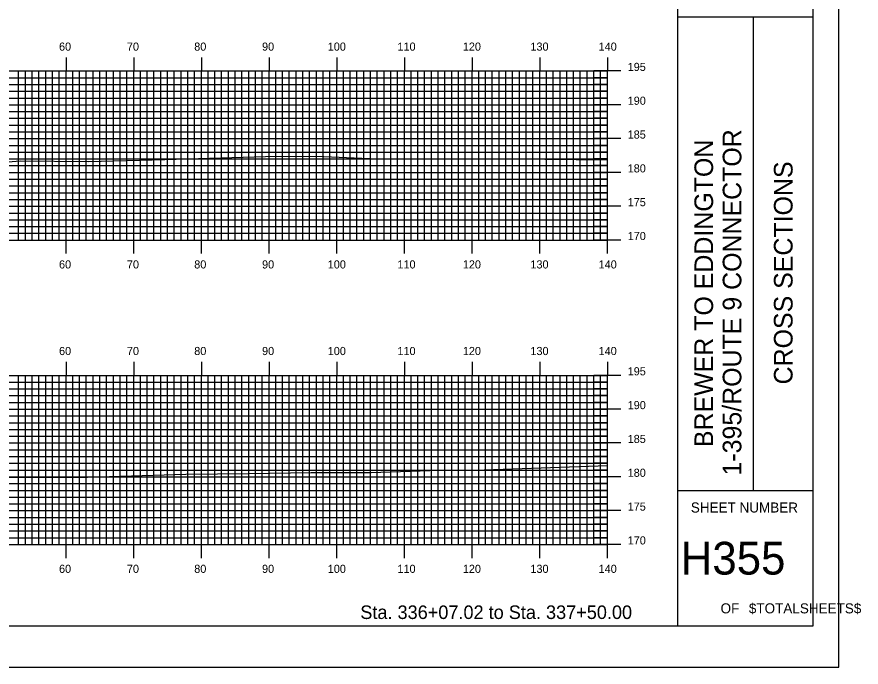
# Model space of a CAD drawing. Extents: x 1823571 to 1823914, y 442310 to 442530.
# Drawn here: x 1823789.6 to 1823914.4, y 442310 to 442406.1 of the extents above; entities that cross this region are included whole.
import ezdxf

# ---------------------------------------------------------------- set-up
doc = ezdxf.new("R2010")
doc.units = 0
for name, color, linetype in [('BORDER', 7, 'Continuous'), ('H_V ANNOTATION', 7, 'Continuous'), ('MAJOR', 7, 'Continuous'), ('MINOR', 7, 'Continuous'), ('PLOT BOUNDARY', 7, 'Continuous'), ('S_Roadway_Centerline', 7, 'Continuous')]:
    doc.layers.add(name, color=color, linetype=linetype)

msp = doc.modelspace()

# ---------------------------------------------------------------- linework, layer by layer
at = {"layer": 'BORDER'}
for p, q in [((1823887.3, 442316.11), (1823887.3, 442526.11)), ((1823887.3, 442406.11), (1823907.3, 442406.11)), ((1823898.48, 442336.11), (1823898.48, 442406.11)), ((1823887.3, 442336.11), (1823907.3, 442336.11))]:
    msp.add_line(p, q, dxfattribs=at)
msp.add_lwpolyline([(1823587.3, 442316.11), (1823907.3, 442316.11), (1823907.3, 442526.11), (1823587.3, 442526.11)], close=True, dxfattribs=at)
at = {"layer": 'MAJOR'}
for p, q in [((1823796.9, 442400.12), (1823796.9, 442398.12)), ((1823806.9, 442400.12), (1823806.9, 442398.12)), ((1823816.9, 442400.12), (1823816.9, 442398.12)), ((1823826.9, 442400.12), (1823826.9, 442398.12)), ((1823836.9, 442400.12), (1823836.9, 442398.12)), ((1823846.9, 442400.12), (1823846.9, 442398.12)), ((1823856.9, 442400.12), (1823856.9, 442398.12)), ((1823866.9, 442400.12), (1823866.9, 442398.12)), ((1823876.9, 442400.12), (1823876.9, 442398.12)), ((1823596.9, 442398.12), (1823876.9, 442398.12)), ((1823596.9, 442398.12), (1823876.9, 442398.12)), ((1823796.9, 442373.12), (1823796.9, 442398.12)), ((1823806.9, 442373.12), (1823806.9, 442398.12)), ((1823816.9, 442373.12), (1823816.9, 442398.12)), ((1823826.9, 442373.12), (1823826.9, 442398.12)), ((1823836.9, 442373.12), (1823836.9, 442398.12)), ((1823846.9, 442373.12), (1823846.9, 442398.12)), ((1823856.9, 442373.12), (1823856.9, 442398.12)), ((1823866.9, 442373.12), (1823866.9, 442398.12)), ((1823878.9, 442398.12), (1823874.9, 442398.12)), ((1823876.9, 442373.12), (1823876.9, 442398.12)), ((1823876.9, 442373.12), (1823876.9, 442398.12)), ((1823596.9, 442393.12), (1823876.9, 442393.12)), ((1823878.9, 442393.12), (1823874.9, 442393.12)), ((1823596.9, 442388.12), (1823876.9, 442388.12)), ((1823878.9, 442388.12), (1823874.9, 442388.12)), ((1823596.9, 442383.12), (1823876.9, 442383.12)), ((1823878.9, 442383.12), (1823874.9, 442383.12)), ((1823596.9, 442378.12), (1823876.9, 442378.12)), ((1823878.9, 442378.12), (1823874.9, 442378.12)), ((1823596.9, 442373.12), (1823876.9, 442373.12)), ((1823796.9, 442371.11), (1823796.9, 442373.12)), ((1823806.9, 442371.11), (1823806.9, 442373.12)), ((1823816.9, 442371.11), (1823816.9, 442373.12)), ((1823826.9, 442371.11), (1823826.9, 442373.12)), ((1823836.9, 442371.11), (1823836.9, 442373.12)), ((1823846.9, 442371.11), (1823846.9, 442373.12)), ((1823856.9, 442371.11), (1823856.9, 442373.12)), ((1823866.9, 442371.11), (1823866.9, 442373.12)), ((1823878.9, 442373.12), (1823874.9, 442373.12)), ((1823876.9, 442371.11), (1823876.9, 442373.12)), ((1823796.9, 442355.12), (1823796.9, 442353.12)), ((1823806.9, 442355.12), (1823806.9, 442353.12)), ((1823816.9, 442355.12), (1823816.9, 442353.12)), ((1823826.9, 442355.12), (1823826.9, 442353.12)), ((1823836.9, 442355.12), (1823836.9, 442353.12)), ((1823846.9, 442355.12), (1823846.9, 442353.12)), ((1823856.9, 442355.12), (1823856.9, 442353.12)), ((1823866.9, 442355.12), (1823866.9, 442353.12)), ((1823876.9, 442355.12), (1823876.9, 442353.12)), ((1823596.9, 442353.12), (1823876.9, 442353.12)), ((1823796.9, 442328.12), (1823796.9, 442353.12)), ((1823806.9, 442328.12), (1823806.9, 442353.12)), ((1823816.9, 442328.12), (1823816.9, 442353.12)), ((1823826.9, 442328.12), (1823826.9, 442353.12)), ((1823836.9, 442328.12), (1823836.9, 442353.12)), ((1823846.9, 442328.12), (1823846.9, 442353.12)), ((1823856.9, 442328.12), (1823856.9, 442353.12)), ((1823866.9, 442328.12), (1823866.9, 442353.12)), ((1823878.9, 442353.12), (1823874.9, 442353.12)), ((1823876.9, 442328.12), (1823876.9, 442353.12)), ((1823876.9, 442328.12), (1823876.9, 442353.12)), ((1823596.9, 442348.12), (1823876.9, 442348.12)), ((1823878.9, 442348.12), (1823874.9, 442348.12)), ((1823596.9, 442343.12), (1823876.9, 442343.12)), ((1823878.9, 442343.12), (1823874.9, 442343.12)), ((1823596.9, 442338.12), (1823876.9, 442338.12)), ((1823878.9, 442338.12), (1823874.9, 442338.12)), ((1823596.9, 442333.12), (1823876.9, 442333.12)), ((1823878.9, 442333.12), (1823874.9, 442333.12)), ((1823596.9, 442328.12), (1823876.9, 442328.12)), ((1823596.9, 442328.12), (1823876.9, 442328.12)), ((1823796.9, 442326.11), (1823796.9, 442328.12)), ((1823806.9, 442326.11), (1823806.9, 442328.12)), ((1823816.9, 442326.11), (1823816.9, 442328.12)), ((1823826.9, 442326.11), (1823826.9, 442328.12)), ((1823836.9, 442326.11), (1823836.9, 442328.12)), ((1823846.9, 442326.11), (1823846.9, 442328.12)), ((1823856.9, 442326.11), (1823856.9, 442328.12)), ((1823866.9, 442326.11), (1823866.9, 442328.12)), ((1823878.9, 442328.12), (1823874.9, 442328.12)), ((1823876.9, 442326.11), (1823876.9, 442328.12))]:
    msp.add_line(p, q, dxfattribs=at)
at = {"layer": 'MINOR'}
for p, q in [((1823789.9, 442373.12), (1823789.9, 442398.12)), ((1823790.9, 442373.12), (1823790.9, 442398.12)), ((1823791.9, 442373.12), (1823791.9, 442398.12)), ((1823792.9, 442373.12), (1823792.9, 442398.12)), ((1823793.9, 442373.12), (1823793.9, 442398.12)), ((1823794.9, 442373.12), (1823794.9, 442398.12)), ((1823795.9, 442373.12), (1823795.9, 442398.12)), ((1823797.9, 442373.12), (1823797.9, 442398.12)), ((1823798.9, 442373.12), (1823798.9, 442398.12)), ((1823799.9, 442373.12), (1823799.9, 442398.12)), ((1823800.9, 442373.12), (1823800.9, 442398.12)), ((1823801.9, 442373.12), (1823801.9, 442398.12)), ((1823802.9, 442373.12), (1823802.9, 442398.12)), ((1823803.9, 442373.12), (1823803.9, 442398.12)), ((1823804.9, 442373.12), (1823804.9, 442398.12)), ((1823805.9, 442373.12), (1823805.9, 442398.12)), ((1823807.9, 442373.12), (1823807.9, 442398.12)), ((1823808.9, 442373.12), (1823808.9, 442398.12)), ((1823809.9, 442373.12), (1823809.9, 442398.12)), ((1823810.9, 442373.12), (1823810.9, 442398.12)), ((1823811.9, 442373.12), (1823811.9, 442398.12)), ((1823812.9, 442373.12), (1823812.9, 442398.12)), ((1823813.9, 442373.12), (1823813.9, 442398.12)), ((1823814.9, 442373.12), (1823814.9, 442398.12)), ((1823815.9, 442373.12), (1823815.9, 442398.12)), ((1823817.9, 442373.12), (1823817.9, 442398.12)), ((1823818.9, 442373.12), (1823818.9, 442398.12)), ((1823819.9, 442373.12), (1823819.9, 442398.12)), ((1823820.9, 442373.12), (1823820.9, 442398.12)), ((1823821.9, 442373.12), (1823821.9, 442398.12)), ((1823822.9, 442373.12), (1823822.9, 442398.12)), ((1823823.9, 442373.12), (1823823.9, 442398.12)), ((1823824.9, 442373.12), (1823824.9, 442398.12)), ((1823825.9, 442373.12), (1823825.9, 442398.12)), ((1823827.9, 442373.12), (1823827.9, 442398.12)), ((1823828.9, 442373.12), (1823828.9, 442398.12)), ((1823829.9, 442373.12), (1823829.9, 442398.12)), ((1823830.9, 442373.12), (1823830.9, 442398.12)), ((1823831.9, 442373.12), (1823831.9, 442398.12)), ((1823832.9, 442373.12), (1823832.9, 442398.12)), ((1823833.9, 442373.12), (1823833.9, 442398.12)), ((1823834.9, 442373.12), (1823834.9, 442398.12)), ((1823835.9, 442373.12), (1823835.9, 442398.12)), ((1823837.9, 442373.12), (1823837.9, 442398.12)), ((1823838.9, 442373.12), (1823838.9, 442398.12)), ((1823839.9, 442373.12), (1823839.9, 442398.12)), ((1823840.9, 442373.12), (1823840.9, 442398.12)), ((1823841.9, 442373.12), (1823841.9, 442398.12)), ((1823842.9, 442373.12), (1823842.9, 442398.12)), ((1823843.9, 442373.12), (1823843.9, 442398.12)), ((1823844.9, 442373.12), (1823844.9, 442398.12)), ((1823845.9, 442373.12), (1823845.9, 442398.12)), ((1823847.9, 442373.12), (1823847.9, 442398.12)), ((1823848.9, 442373.12), (1823848.9, 442398.12)), ((1823849.9, 442373.12), (1823849.9, 442398.12)), ((1823850.9, 442373.12), (1823850.9, 442398.12)), ((1823851.9, 442373.12), (1823851.9, 442398.12)), ((1823852.9, 442373.12), (1823852.9, 442398.12)), ((1823853.9, 442373.12), (1823853.9, 442398.12)), ((1823854.9, 442373.12), (1823854.9, 442398.12)), ((1823855.9, 442373.12), (1823855.9, 442398.12)), ((1823857.9, 442373.12), (1823857.9, 442398.12)), ((1823858.9, 442373.12), (1823858.9, 442398.12)), ((1823859.9, 442373.12), (1823859.9, 442398.12)), ((1823860.9, 442373.12), (1823860.9, 442398.12)), ((1823861.9, 442373.12), (1823861.9, 442398.12)), ((1823862.9, 442373.12), (1823862.9, 442398.12)), ((1823863.9, 442373.12), (1823863.9, 442398.12)), ((1823864.9, 442373.12), (1823864.9, 442398.12)), ((1823865.9, 442373.12), (1823865.9, 442398.12)), ((1823867.9, 442373.12), (1823867.9, 442398.12)), ((1823868.9, 442373.12), (1823868.9, 442398.12)), ((1823869.9, 442373.12), (1823869.9, 442398.12)), ((1823870.9, 442373.12), (1823870.9, 442398.12)), ((1823871.9, 442373.12), (1823871.9, 442398.12)), ((1823872.9, 442373.12), (1823872.9, 442398.12)), ((1823873.9, 442373.12), (1823873.9, 442398.12)), ((1823874.9, 442373.12), (1823874.9, 442398.12)), ((1823875.9, 442373.12), (1823875.9, 442398.12)), ((1823596.9, 442397.12), (1823876.9, 442397.12)), ((1823876.9, 442397.12), (1823874.9, 442397.12)), ((1823596.9, 442396.12), (1823876.9, 442396.12)), ((1823876.9, 442396.12), (1823874.9, 442396.12)), ((1823596.9, 442395.12), (1823876.9, 442395.12)), ((1823876.9, 442395.12), (1823874.9, 442395.12)), ((1823596.9, 442394.12), (1823876.9, 442394.12)), ((1823876.9, 442394.12), (1823874.9, 442394.12)), ((1823596.9, 442392.12), (1823876.9, 442392.12)), ((1823876.9, 442392.12), (1823874.9, 442392.12)), ((1823596.9, 442391.12), (1823876.9, 442391.12)), ((1823876.9, 442391.12), (1823874.9, 442391.12)), ((1823596.9, 442390.12), (1823876.9, 442390.12)), ((1823876.9, 442390.12), (1823874.9, 442390.12)), ((1823596.9, 442389.12), (1823876.9, 442389.12)), ((1823876.9, 442389.12), (1823874.9, 442389.12)), ((1823596.9, 442387.12), (1823876.9, 442387.12)), ((1823876.9, 442387.12), (1823874.9, 442387.12)), ((1823876.9, 442387.12), (1823876.9, 442387.12)), ((1823596.9, 442386.12), (1823876.9, 442386.12)), ((1823876.9, 442386.12), (1823874.9, 442386.12)), ((1823596.9, 442385.12), (1823876.9, 442385.12)), ((1823876.9, 442385.12), (1823874.9, 442385.12)), ((1823596.9, 442384.12), (1823876.9, 442384.12)), ((1823876.9, 442384.12), (1823874.9, 442384.12)), ((1823596.9, 442382.12), (1823876.9, 442382.12)), ((1823876.9, 442382.12), (1823874.9, 442382.12)), ((1823596.9, 442381.12), (1823876.9, 442381.12)), ((1823876.9, 442381.12), (1823874.9, 442381.12)), ((1823596.9, 442380.12), (1823876.9, 442380.12)), ((1823876.9, 442380.12), (1823874.9, 442380.12)), ((1823596.9, 442379.12), (1823876.9, 442379.12)), ((1823876.9, 442379.12), (1823874.9, 442379.12)), ((1823596.9, 442377.12), (1823876.9, 442377.12)), ((1823876.9, 442377.12), (1823874.9, 442377.12)), ((1823596.9, 442376.12), (1823876.9, 442376.12)), ((1823876.9, 442376.12), (1823874.9, 442376.12)), ((1823596.9, 442375.12), (1823876.9, 442375.12)), ((1823876.9, 442375.12), (1823874.9, 442375.12)), ((1823596.9, 442374.12), (1823876.9, 442374.12)), ((1823876.9, 442374.12), (1823874.9, 442374.12)), ((1823596.9, 442352.12), (1823876.9, 442352.12)), ((1823789.9, 442328.12), (1823789.9, 442353.12)), ((1823790.9, 442328.12), (1823790.9, 442353.12)), ((1823791.9, 442328.12), (1823791.9, 442353.12)), ((1823792.9, 442328.12), (1823792.9, 442353.12)), ((1823793.9, 442328.12), (1823793.9, 442353.12)), ((1823794.9, 442328.12), (1823794.9, 442353.12)), ((1823795.9, 442328.12), (1823795.9, 442353.12)), ((1823797.9, 442328.12), (1823797.9, 442353.12)), ((1823798.9, 442328.12), (1823798.9, 442353.12)), ((1823799.9, 442328.12), (1823799.9, 442353.12)), ((1823800.9, 442328.12), (1823800.9, 442353.12)), ((1823801.9, 442328.12), (1823801.9, 442353.12)), ((1823802.9, 442328.12), (1823802.9, 442353.12)), ((1823803.9, 442328.12), (1823803.9, 442353.12)), ((1823804.9, 442328.12), (1823804.9, 442353.12)), ((1823805.9, 442328.12), (1823805.9, 442353.12)), ((1823807.9, 442328.12), (1823807.9, 442353.12)), ((1823808.9, 442328.12), (1823808.9, 442353.12)), ((1823809.9, 442328.12), (1823809.9, 442353.12)), ((1823810.9, 442328.12), (1823810.9, 442353.12)), ((1823811.9, 442328.12), (1823811.9, 442353.12)), ((1823812.9, 442328.12), (1823812.9, 442353.12)), ((1823813.9, 442328.12), (1823813.9, 442353.12)), ((1823814.9, 442328.12), (1823814.9, 442353.12)), ((1823815.9, 442328.12), (1823815.9, 442353.12)), ((1823817.9, 442328.12), (1823817.9, 442353.12)), ((1823818.9, 442328.12), (1823818.9, 442353.12)), ((1823819.9, 442328.12), (1823819.9, 442353.12)), ((1823820.9, 442328.12), (1823820.9, 442353.12)), ((1823821.9, 442328.12), (1823821.9, 442353.12)), ((1823822.9, 442328.12), (1823822.9, 442353.12)), ((1823823.9, 442328.12), (1823823.9, 442353.12)), ((1823824.9, 442328.12), (1823824.9, 442353.12)), ((1823825.9, 442328.12), (1823825.9, 442353.12)), ((1823827.9, 442328.12), (1823827.9, 442353.12)), ((1823828.9, 442328.12), (1823828.9, 442353.12)), ((1823829.9, 442328.12), (1823829.9, 442353.12)), ((1823830.9, 442328.12), (1823830.9, 442353.12)), ((1823831.9, 442328.12), (1823831.9, 442353.12)), ((1823832.9, 442328.12), (1823832.9, 442353.12)), ((1823833.9, 442328.12), (1823833.9, 442353.12)), ((1823834.9, 442328.12), (1823834.9, 442353.12)), ((1823835.9, 442328.12), (1823835.9, 442353.12)), ((1823837.9, 442328.12), (1823837.9, 442353.12)), ((1823838.9, 442328.12), (1823838.9, 442353.12)), ((1823839.9, 442328.12), (1823839.9, 442353.12)), ((1823840.9, 442328.12), (1823840.9, 442353.12)), ((1823841.9, 442328.12), (1823841.9, 442353.12)), ((1823842.9, 442328.12), (1823842.9, 442353.12)), ((1823843.9, 442328.12), (1823843.9, 442353.12)), ((1823844.9, 442328.12), (1823844.9, 442353.12)), ((1823845.9, 442328.12), (1823845.9, 442353.12)), ((1823847.9, 442328.12), (1823847.9, 442353.12)), ((1823848.9, 442328.12), (1823848.9, 442353.12)), ((1823849.9, 442328.12), (1823849.9, 442353.12)), ((1823850.9, 442328.12), (1823850.9, 442353.12)), ((1823851.9, 442328.12), (1823851.9, 442353.12)), ((1823852.9, 442328.12), (1823852.9, 442353.12)), ((1823853.9, 442328.12), (1823853.9, 442353.12)), ((1823854.9, 442328.12), (1823854.9, 442353.12)), ((1823855.9, 442328.12), (1823855.9, 442353.12)), ((1823857.9, 442328.12), (1823857.9, 442353.12)), ((1823858.9, 442328.12), (1823858.9, 442353.12)), ((1823859.9, 442328.12), (1823859.9, 442353.12)), ((1823860.9, 442328.12), (1823860.9, 442353.12)), ((1823861.9, 442328.12), (1823861.9, 442353.12)), ((1823862.9, 442328.12), (1823862.9, 442353.12)), ((1823863.9, 442328.12), (1823863.9, 442353.12)), ((1823864.9, 442328.12), (1823864.9, 442353.12)), ((1823865.9, 442328.12), (1823865.9, 442353.12)), ((1823867.9, 442328.12), (1823867.9, 442353.12)), ((1823868.9, 442328.12), (1823868.9, 442353.12)), ((1823869.9, 442328.12), (1823869.9, 442353.12)), ((1823870.9, 442328.12), (1823870.9, 442353.12)), ((1823871.9, 442328.12), (1823871.9, 442353.12)), ((1823872.9, 442328.12), (1823872.9, 442353.12)), ((1823873.9, 442328.12), (1823873.9, 442353.12)), ((1823874.9, 442328.12), (1823874.9, 442353.12)), ((1823876.9, 442352.12), (1823874.9, 442352.12)), ((1823875.9, 442328.12), (1823875.9, 442353.12)), ((1823596.9, 442351.12), (1823876.9, 442351.12)), ((1823876.9, 442351.12), (1823874.9, 442351.12)), ((1823596.9, 442350.12), (1823876.9, 442350.12)), ((1823876.9, 442350.12), (1823874.9, 442350.12)), ((1823596.9, 442349.12), (1823876.9, 442349.12)), ((1823876.9, 442349.12), (1823874.9, 442349.12)), ((1823596.9, 442347.12), (1823876.9, 442347.12)), ((1823876.9, 442347.12), (1823874.9, 442347.12)), ((1823596.9, 442346.12), (1823876.9, 442346.12)), ((1823876.9, 442346.12), (1823874.9, 442346.12)), ((1823596.9, 442345.12), (1823876.9, 442345.12)), ((1823876.9, 442345.12), (1823874.9, 442345.12)), ((1823596.9, 442344.12), (1823876.9, 442344.12)), ((1823876.9, 442344.12), (1823874.9, 442344.12)), ((1823596.9, 442342.12), (1823876.9, 442342.12)), ((1823876.9, 442342.12), (1823874.9, 442342.12)), ((1823596.9, 442341.12), (1823876.9, 442341.12)), ((1823876.9, 442341.12), (1823874.9, 442341.12)), ((1823596.9, 442340.12), (1823876.9, 442340.12)), ((1823876.9, 442340.12), (1823874.9, 442340.12)), ((1823596.9, 442339.12), (1823876.9, 442339.12)), ((1823876.9, 442339.12), (1823874.9, 442339.12)), ((1823596.9, 442337.12), (1823876.9, 442337.12)), ((1823876.9, 442337.12), (1823874.9, 442337.12)), ((1823596.9, 442336.12), (1823876.9, 442336.12)), ((1823876.9, 442336.12), (1823874.9, 442336.12)), ((1823596.9, 442335.12), (1823876.9, 442335.12)), ((1823876.9, 442335.12), (1823874.9, 442335.12)), ((1823596.9, 442334.12), (1823876.9, 442334.12)), ((1823876.9, 442334.12), (1823874.9, 442334.12)), ((1823596.9, 442332.12), (1823876.9, 442332.12)), ((1823876.9, 442332.12), (1823874.9, 442332.12)), ((1823596.9, 442331.12), (1823876.9, 442331.12)), ((1823876.9, 442331.12), (1823874.9, 442331.12)), ((1823596.9, 442330.12), (1823876.9, 442330.12)), ((1823876.9, 442330.12), (1823874.9, 442330.12)), ((1823596.9, 442329.12), (1823876.9, 442329.12)), ((1823876.9, 442329.12), (1823874.9, 442329.12))]:
    msp.add_line(p, q, dxfattribs=at)
at = {"layer": 'PLOT BOUNDARY'}
msp.add_lwpolyline([(1823571.11, 442309.99), (1823911.11, 442309.99), (1823911.11, 442529.99), (1823571.11, 442529.99)], close=True, dxfattribs=at)
at = {"layer": 'S_Roadway_Centerline'}
for points in [[(1823784.7, 442384.41), (1823790.13, 442384.85), (1823800.21, 442384.75), (1823811.5, 442385.03), (1823826.37, 442385.46), (1823833.88, 442385.5), (1823841.74, 442385.17), (1823863.03, 442385.11), (1823876.9, 442384.99)], [(1823779.49, 442337.91), (1823792.94, 442338.07), (1823800.09, 442338.07), (1823804.94, 442338.24), (1823814.63, 442338.53), (1823823.96, 442338.63), (1823833.12, 442338.76), (1823842.01, 442338.78), (1823850.68, 442339.04), (1823858.67, 442339.17), (1823876.9, 442339.77)]]:
    msp.add_lwpolyline(points, dxfattribs=at)

# ---------------------------------------------------------------- texts
at = {"layer": 'BORDER'}
for s, p in [('1-395/ROUTE 9 CONNECTOR', (1823896.7, 442338.31)), ('BREWER TO EDDINGTON', (1823892.52, 442342.51)), ('CROSS SECTIONS', (1823904.27, 442351.78))]:
    msp.add_text(s, height=2.7557, rotation=90, dxfattribs=at).set_placement(p)
for s, height, p in [('SHEET NUMBER', 1.4905, (1823889.23, 442332.84)), ('H355', 4.839, (1823887.74, 442323.67)), ('$TOTALSHEETS$', 1.4905, (1823897.81, 442317.93)), ('OF', 1.491, (1823893.63, 442317.93))]:
    msp.add_text(s, height=height, dxfattribs=at).set_placement(p)
at = {"layer": 'H_V ANNOTATION'}
for s, height, p in [('60', 1.2, (1823795.87, 442401.12)), ('70', 1.2, (1823805.9, 442401.12)), ('80', 1.2, (1823815.85, 442401.12)), ('90', 1.2, (1823825.87, 442401.12)), ('100', 1.2, (1823835.58, 442401.12)), ('110', 1.2, (1823845.88, 442401.12)), ('120', 1.2, (1823855.54, 442401.12)), ('130', 1.2, (1823865.53, 442401.12)), ('140', 1.2, (1823875.61, 442401.12)), ('195', 1.2, (1823879.9, 442398.12)), ('190', 1.2, (1823879.9, 442393.12)), ('185', 1.2, (1823879.9, 442388.12)), ('180', 1.2, (1823879.9, 442383.12)), ('175', 1.2, (1823879.9, 442378.12)), ('170', 1.2, (1823879.9, 442373.12)), ('60', 1.2, (1823795.87, 442368.92)), ('70', 1.2, (1823805.9, 442368.92)), ('80', 1.2, (1823815.85, 442368.92)), ('90', 1.2, (1823825.87, 442368.92)), ('100', 1.2, (1823835.58, 442368.92)), ('110', 1.2, (1823845.88, 442368.92)), ('120', 1.2, (1823855.54, 442368.92)), ('130', 1.2, (1823865.53, 442368.92)), ('140', 1.2, (1823875.61, 442368.92)), ('60', 1.2, (1823795.87, 442356.12)), ('70', 1.2, (1823805.9, 442356.12)), ('80', 1.2, (1823815.85, 442356.12)), ('90', 1.2, (1823825.87, 442356.12)), ('100', 1.2, (1823835.58, 442356.12)), ('110', 1.2, (1823845.88, 442356.12)), ('120', 1.2, (1823855.54, 442356.12)), ('130', 1.2, (1823865.53, 442356.12)), ('140', 1.2, (1823875.61, 442356.12)), ('195', 1.2, (1823879.9, 442353.12)), ('190', 1.2, (1823879.9, 442348.12)), ('185', 1.2, (1823879.9, 442343.12)), ('180', 1.2, (1823879.9, 442338.12)), ('175', 1.2, (1823879.9, 442333.12)), ('170', 1.2, (1823879.9, 442328.12)), ('60', 1.2, (1823795.87, 442323.92)), ('70', 1.2, (1823805.9, 442323.92)), ('80', 1.2, (1823815.85, 442323.92)), ('90', 1.2, (1823825.87, 442323.92)), ('100', 1.2, (1823835.58, 442323.92)), ('110', 1.2, (1823845.88, 442323.92)), ('120', 1.2, (1823855.54, 442323.92)), ('130', 1.2, (1823865.53, 442323.92)), ('140', 1.2, (1823875.61, 442323.92)), ('Sta. 336+07.02 to Sta. 337+50.00', 2.0004, (1823840.39, 442317.1))]:
    msp.add_text(s, height=height, dxfattribs=at).set_placement(p)

doc.saveas('drawing.dxf')
